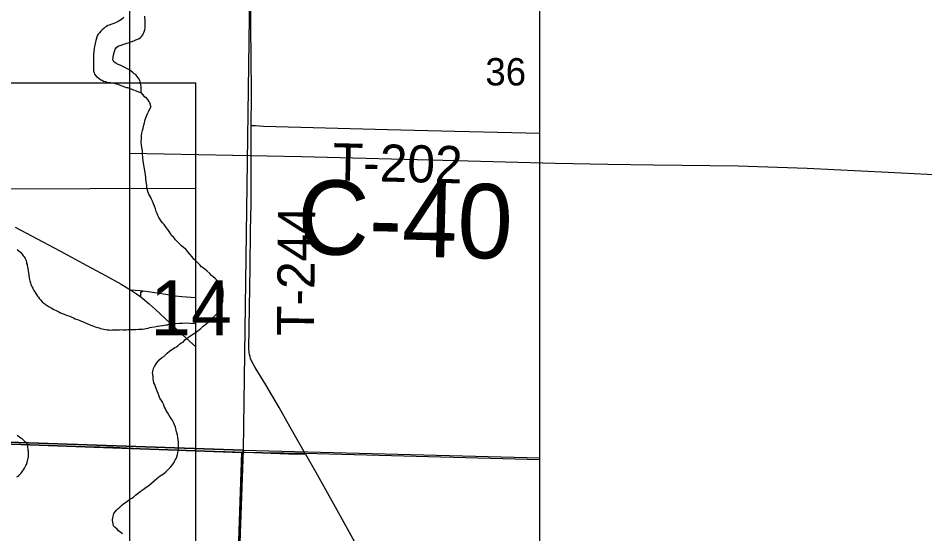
# Model space of a CAD drawing. Extents: x 0 to 68, y 0 to 52.9.
# Drawn here: x 49.292 to 51.122, y 37.625 to 38.666 of the extents above; entities that cross this region are included whole.
import ezdxf

# ---------------------------------------------------------------- set-up
doc = ezdxf.new("R2010")
doc.units = 0
for name, color, linetype in [('Default', 7, 'Continuous'), ('GM_X_County_Road', 7, 'Continuous'), ('GM_X_County_Road_Text', 7, 'Continuous'), ('GM_X_Minor_River', 7, 'Continuous'), ('GM_X_State_Route', 7, 'Continuous'), ('GM_X_Township', 7, 'Continuous'), ('GM_X_Township_Road', 7, 'Continuous'), ('GM_X_Township_Road_Text', 7, 'Continuous')]:
    doc.layers.add(name, color=color, linetype=linetype)

msp = doc.modelspace()

# ---------------------------------------------------------------- linework, layer by layer
at = {"layer": 'Default'}
for p, q in [((49.5172, 34.4614), (49.5172, 52.9414)), ((50.3451, 32.7683), (50.3451, 42.0083)), ((42.2581, 38.5351), (49.6501, 38.5351)), ((49.6501, 31.1431), (49.6501, 38.5351))]:
    msp.add_line(p, q, dxfattribs=at)
for points in [[(49.764, 39.105), (49.7457, 37.7942), (48.4264, 37.8391), (48.4576, 39.1473)], [(48.4264, 37.8391), (49.7457, 37.7942), (49.6996, 36.5084), (48.3843, 36.5523)]]:
    msp.add_lwpolyline(points, close=True, dxfattribs=at)
for points in [[(49.5047, 38.6669), (49.5001, 38.6634), (49.4935, 38.659), (49.488, 38.6565), (49.4753, 38.6517), (49.4723, 38.6507), (49.4697, 38.6492), (49.4672, 38.6473), (49.4642, 38.6448), (49.4611, 38.6423), (49.4585, 38.6393), (49.4555, 38.6364), (49.4529, 38.6334), (49.4514, 38.6299), (49.4498, 38.6254), (49.4482, 38.6204), (49.4472, 38.6144), (49.4456, 38.6089), (49.445, 38.6044), (49.4444, 38.5983), (49.4438, 38.5923), (49.4438, 38.5868), (49.4437, 38.5803), (49.4436, 38.5753), (49.4436, 38.5707), (49.4435, 38.5657), (49.4439, 38.5597), (49.4449, 38.5556), (49.4459, 38.5531), (49.4498, 38.548), (49.4543, 38.5445), (49.4588, 38.5414), (49.4613, 38.5404), (49.4638, 38.5388), (49.4678, 38.5378), (49.4708, 38.5367), (49.4739, 38.5362), (49.4779, 38.5361), (49.4809, 38.5356), (49.4839, 38.535), (49.4869, 38.534), (49.4904, 38.5334), (49.493, 38.5329), (49.4975, 38.5308), (49.501, 38.5293), (49.5035, 38.5283), (49.506, 38.5272), (49.5095, 38.5262), (49.512, 38.5256), (49.5396, 38.5152)], [(49.5162, 38.617), (49.5187, 38.618), (49.5217, 38.6189), (49.5263, 38.6209), (49.5293, 38.6218), (49.5334, 38.6233), (49.5359, 38.6248), (49.5385, 38.6267), (49.541, 38.6292), (49.5431, 38.6322), (49.5446, 38.6352), (49.5462, 38.6382), (49.5472, 38.6422), (49.5478, 38.6462), (49.5478, 38.6502), (49.5479, 38.6542), (49.5479, 38.6578), (49.548, 38.6623), (49.5475, 38.6658), (49.5471, 38.6698)], [(49.5396, 38.5152), (49.5401, 38.5212), (49.5397, 38.5283), (49.5393, 38.5313), (49.5388, 38.5348), (49.5369, 38.5399), (49.5344, 38.5449), (49.5314, 38.5485), (49.529, 38.552), (49.526, 38.5536), (49.5235, 38.5556), (49.52, 38.5587), (49.5175, 38.5602), (49.515, 38.5623), (49.5115, 38.5638), (49.507, 38.5659), (49.504, 38.5679), (49.5005, 38.5695), (49.4975, 38.571), (49.4935, 38.5726), (49.489, 38.5747), (49.4855, 38.5772), (49.483, 38.5818), (49.4836, 38.5873), (49.4841, 38.5918), (49.4873, 38.6033), (49.4904, 38.6068), (49.4939, 38.6102), (49.4975, 38.6107), (49.5015, 38.6122), (49.5045, 38.6131), (49.5076, 38.6141), (49.5106, 38.615), (49.5136, 38.616), (49.5162, 38.617)], [(49.6501, 38.3219), (49.2232, 38.3205), (49.2258, 38.5351)], [(49.5396, 38.5152), (49.5455, 38.5086), (49.5485, 38.5066), (49.553, 38.5015), (49.555, 38.4984), (49.5564, 38.4959), (49.5574, 38.4934), (49.5584, 38.4904), (49.5594, 38.4873), (49.5533, 38.4746)], [(49.5449, 38.447), (49.5454, 38.4496), (49.5459, 38.4521), (49.5469, 38.4551), (49.5474, 38.4581), (49.5479, 38.4611), (49.5494, 38.4646), (49.5533, 38.4746)], [(49.6015, 37.9969), (49.6051, 37.9994), (49.6081, 38.0014), (49.6111, 38.0029), (49.6136, 38.0044), (49.6176, 38.0079), (49.6206, 38.0104), (49.6247, 38.0123), (49.6282, 38.0169), (49.6352, 38.0218), (49.6423, 38.0268), (49.6488, 38.0308), (49.6548, 38.0358), (49.6604, 38.0398), (49.6654, 38.0443), (49.6704, 38.0483), (49.6754, 38.0523), (49.68, 38.0558), (49.683, 38.0588), (49.686, 38.0623), (49.69, 38.0663), (49.693, 38.0693), (49.6961, 38.0728), (49.6976, 38.0753), (49.6996, 38.0788), (49.7011, 38.0813), (49.7026, 38.0843), (49.7036, 38.0888), (49.7046, 38.0939), (49.7051, 38.0994), (49.7052, 38.1069), (49.7052, 38.1134), (49.7047, 38.1194), (49.7032, 38.124), (49.7012, 38.1285), (49.6987, 38.1315), (49.6892, 38.1406), (49.6852, 38.1436), (49.6817, 38.1466), (49.6782, 38.1506), (49.6727, 38.1557), (49.6692, 38.1587), (49.6657, 38.1612), (49.6616, 38.1642), (49.6581, 38.1683), (49.6541, 38.1723), (49.6501, 38.1763), (49.6461, 38.1798), (49.6426, 38.1844), (49.6381, 38.1899), (49.6341, 38.1944), (49.6301, 38.1994), (49.6251, 38.203), (49.6216, 38.2065), (49.6171, 38.2105), (49.6131, 38.2146), (49.6091, 38.2186), (49.6056, 38.2231), (49.6021, 38.2266), (49.5991, 38.2312), (49.5961, 38.2352), (49.5936, 38.2392), (49.5901, 38.2437), (49.5861, 38.2493), (49.5831, 38.2528), (49.5806, 38.2563), (49.5781, 38.2593), (49.5756, 38.2633), (49.5736, 38.2674), (49.5721, 38.2719), (49.5701, 38.2759), (49.5686, 38.2809), (49.5666, 38.2864), (49.5646, 38.291), (49.5631, 38.2965), (49.5606, 38.3005), (49.5591, 38.304), (49.5571, 38.3075), (49.5551, 38.3106), (49.5541, 38.3141), (49.5526, 38.3186), (49.5516, 38.3231), (49.5511, 38.3291), (49.5501, 38.3357), (49.5492, 38.3427), (49.5487, 38.3502), (49.5442, 38.3773), (49.5432, 38.3843), (49.5428, 38.3914), (49.5423, 38.3984), (49.5413, 38.4049), (49.5408, 38.4099), (49.5398, 38.414), (49.5398, 38.4175), (49.5403, 38.421), (49.5403, 38.4255), (49.5408, 38.429), (49.5413, 38.434), (49.5424, 38.439), (49.5439, 38.4435), (49.5449, 38.447)], [(49.5023, 37.625), (49.4998, 37.627), (49.4968, 37.629), (49.4943, 37.6315), (49.4913, 37.6345), (49.4873, 37.6381), (49.4843, 37.6411), (49.4833, 37.6456), (49.4828, 37.6491), (49.4823, 37.6521), (49.4823, 37.6546), (49.4828, 37.6571), (49.4834, 37.6607), (49.4849, 37.6662), (49.4874, 37.6697), (49.4904, 37.6727), (49.4934, 37.6762), (49.4969, 37.6792), (49.5005, 37.6822), (49.505, 37.6862), (49.5105, 37.6897), (49.5166, 37.6942), (49.5211, 37.6971), (49.5251, 37.7001), (49.5286, 37.7031), (49.5341, 37.7071), (49.5382, 37.7106), (49.5437, 37.7146), (49.5497, 37.7191), (49.5553, 37.7231), (49.5713, 37.7371), (49.5784, 37.7421), (49.5849, 37.7466), (49.5899, 37.7506), (49.594, 37.7546), (49.5975, 37.7581), (49.6, 37.7606), (49.6015, 37.7631), (49.6035, 37.7656), (49.6065, 37.7691), (49.6081, 37.7731), (49.6096, 37.7756), (49.6116, 37.7806), (49.6131, 37.7856), (49.6141, 37.7891), (49.6146, 37.7922), (49.6151, 37.7957), (49.6151, 37.8002), (49.6152, 37.8052), (49.6152, 37.8102), (49.6147, 37.8147), (49.6142, 37.8197), (49.6132, 37.8253), (49.6112, 37.8313), (49.6092, 37.8408), (49.6057, 37.8484), (49.6022, 37.8554), (49.5987, 37.8609), (49.5957, 37.8655), (49.5932, 37.87), (49.5907, 37.874), (49.5882, 37.8785), (49.5862, 37.882), (49.5847, 37.8866), (49.5827, 37.8906), (49.5807, 37.8941), (49.5777, 37.8991), (49.5762, 37.9031), (49.5742, 37.9082), (49.5723, 37.9132), (49.5703, 37.9182), (49.5688, 37.9217), (49.5673, 37.9263), (49.5658, 37.9298), (49.5648, 37.9338), (49.5643, 37.9383), (49.5638, 37.9428), (49.5628, 37.9503), (49.5633, 37.9529), (49.5638, 37.9559), (49.5648, 37.9589), (49.5668, 37.9629), (49.5699, 37.9684), (49.5754, 37.9754), (49.5809, 37.9804), (49.5855, 37.9829), (49.588, 37.9854), (49.5925, 37.9899), (49.597, 37.9939), (49.6015, 37.9969)], [(49.2887, 37.7403), (49.2928, 37.7422), (49.2948, 37.745), (49.2969, 37.747), (49.2989, 37.7494), (49.3006, 37.7518), (49.3026, 37.7546), (49.3043, 37.7578), (49.3059, 37.7606), (49.3071, 37.7629), (49.3084, 37.7653), (49.3096, 37.7689), (49.3113, 37.7754), (49.3118, 37.7778), (49.3122, 37.7802), (49.3122, 37.7834), (49.3123, 37.7866), (49.3123, 37.7894), (49.3123, 37.7918), (49.312, 37.7938), (49.312, 37.7958), (49.3112, 37.7999), (49.3109, 37.8019), (49.3101, 37.8043), (49.3097, 37.8063), (49.3081, 37.8087), (49.3061, 37.8104), (49.3038, 37.8132), (49.3018, 37.8149), (49.2994, 37.8169), (49.297, 37.8185), (49.2946, 37.8202), (49.2922, 37.8218), (49.2894, 37.8235)], [(50.3451, 36.4776), (49.6996, 36.5084), (49.7457, 37.7942), (50.3451, 37.7786)]]:
    msp.add_lwpolyline(points, dxfattribs=at)
at = {"layer": 'GM_X_County_Road'}
for points in [[(49.5172, 38.3936), (49.8634, 38.3865), (50.175, 38.3783), (50.3759, 38.3731), (50.4819, 38.3714)], [(50.4819, 38.3714), (50.5742, 38.3699), (50.7454, 38.3675), (50.8848, 38.363), (51.0482, 38.3553), (51.1794, 38.3484), (51.7594, 38.3186), (52.1274, 38.2999), (52.1467, 38.299)], [(49.5186, 38.1175), (49.5277, 38.1169), (49.5381, 38.1163), (49.5431, 38.1157)], [(49.5389, 38.1032), (49.539, 38.1082), (49.5392, 38.1104), (49.5395, 38.1114), (49.5404, 38.1134), (49.5431, 38.1157)], [(49.5431, 38.1157), (49.5538, 38.1145), (49.5894, 38.1086), (49.6089, 38.1055), (49.6219, 38.104), (49.6501, 38.1023)]]:
    msp.add_lwpolyline(points, dxfattribs=at)
at = {"layer": 'GM_X_Minor_River'}
for points in [[(49.2897, 38.1991), (49.2929, 38.1963), (49.2961, 38.1938), (49.2992, 38.1902), (49.302, 38.1861), (49.304, 38.1841), (49.3056, 38.1808), (49.3072, 38.178), (49.3075, 38.176), (49.3083, 38.1732), (49.3087, 38.1708), (49.3095, 38.1687), (49.3098, 38.1667), (49.3102, 38.1643), (49.311, 38.1607), (49.3128, 38.1474), (49.3139, 38.1414), (49.3151, 38.1357), (49.3162, 38.1317), (49.3174, 38.1289), (49.3186, 38.1256), (49.3198, 38.1232), (49.3209, 38.1208), (49.3217, 38.1188), (49.3233, 38.1163), (49.3249, 38.1139), (49.3272, 38.1102), (49.3284, 38.1082), (49.3308, 38.1046), (49.3324, 38.1025), (49.3344, 38.0997), (49.3364, 38.0977), (49.3403, 38.0932), (49.3431, 38.0907), (49.3451, 38.0891), (49.3475, 38.0875), (49.3499, 38.0858), (49.3519, 38.0846), (49.3543, 38.0834), (49.3571, 38.0817), (49.3595, 38.0805), (49.3623, 38.0788), (49.3651, 38.0772), (49.3683, 38.076), (49.3707, 38.0743), (49.3739, 38.0731), (49.3771, 38.0714), (49.3811, 38.0698), (49.3859, 38.0681), (49.3911, 38.066), (49.3956, 38.0643), (49.4, 38.0623), (49.4036, 38.061), (49.4068, 38.0594), (49.4112, 38.0577), (49.4144, 38.0565), (49.4176, 38.0548), (49.4212, 38.0536), (49.424, 38.0523), (49.4272, 38.0511), (49.4304, 38.0494), (49.4416, 38.0449)], [(49.4416, 38.0449), (49.4444, 38.044), (49.4472, 38.0428), (49.4517, 38.0415), (49.4549, 38.0407), (49.4581, 38.0398), (49.4609, 38.039), (49.4645, 38.0381), (49.4677, 38.0373), (49.4713, 38.0372), (49.475, 38.0368), (49.4786, 38.0363), (49.4814, 38.0367), (49.4842, 38.0367), (49.4887, 38.0366), (49.4923, 38.037), (49.4959, 38.0369), (49.4995, 38.0373), (49.5032, 38.0372), (49.5068, 38.0372), (49.5104, 38.0371), (49.5137, 38.0375), (49.5177, 38.0374), (49.5217, 38.0374), (49.5253, 38.0377), (49.529, 38.0377), (49.5342, 38.038), (49.5382, 38.038), (49.5423, 38.0383), (49.5467, 38.0387), (49.5503, 38.0394), (49.554, 38.0402), (49.5576, 38.0413), (49.5616, 38.0421), (49.5669, 38.0432), (49.573, 38.0443), (49.5778, 38.0451), (49.5834, 38.0458), (49.5871, 38.0466), (49.5903, 38.0469), (49.5931, 38.0473), (49.596, 38.0481), (49.6, 38.0484), (49.6048, 38.0491), (49.6089, 38.0495), (49.6165, 38.0502), (49.6198, 38.0506), (49.6234, 38.0505), (49.629, 38.0508), (49.6501, 38.0498)]]:
    msp.add_lwpolyline(points, dxfattribs=at)
at = {"layer": 'GM_X_State_Route'}
msp.add_lwpolyline([(49.2858, 38.2442), (49.3755, 38.1963), (49.4305, 38.1669), (49.4681, 38.1467), (49.4996, 38.129), (49.5186, 38.1175), (49.5302, 38.1097), (49.5389, 38.1032), (49.5434, 38.0999), (49.5561, 38.0895), (49.5685, 38.0787), (49.5877, 38.0607), (49.6232, 38.0266), (49.6501, 38.0023)], dxfattribs=at)
at = {"layer": 'GM_X_Township'}
for points in [[(50.3451, 37.7743), (49.87, 37.7873), (49.7424, 37.7891), (49.0919, 37.8129), (48.4292, 37.8378), (47.9758, 37.8521), (47.0934, 37.8749), (46.4354, 37.887), (45.7815, 37.9075), (45.7636, 37.9078), (44.7776, 37.9316), (44.1214, 37.9431), (43.3203, 37.9479), (43.3145, 37.9477), (43.1323, 37.9511), (43.1372, 38.1253), (43.1394, 38.1865), (43.1395, 38.194), (43.1504, 38.6162), (43.1581, 38.8961)], [(44.7776, 37.9316), (45.7636, 37.9078), (45.7815, 37.9075), (46.4354, 37.887), (47.0934, 37.8749), (47.9758, 37.8521), (48.4292, 37.8378), (49.0919, 37.8129), (49.7424, 37.7891), (49.7157, 36.9972), (49.7077, 36.748), (49.6951, 36.1805), (49.6872, 35.8521), (49.6545, 34.5254), (49.6326, 33.8658), (49.6189, 33.2067), (49.6098, 32.7683)]]:
    msp.add_lwpolyline(points, dxfattribs=at)
at = {"layer": 'GM_X_Township_Road'}
for points in [[(49.7623, 38.4494), (49.7624, 38.5084), (49.7617, 38.5946), (49.7613, 38.6397), (49.7616, 38.6931), (49.7624, 38.7464), (49.7623, 38.7996), (49.7632, 38.902), (49.7643, 39.0211), (49.7647, 39.0744), (49.7653, 39.1063)], [(49.8719, 37.7861), (49.841, 37.8408), (49.8186, 37.88), (49.7914, 37.9259), (49.7698, 37.9609), (49.7641, 37.9718), (49.7609, 37.9793), (49.7597, 37.9832), (49.7587, 37.9872), (49.758, 37.9912), (49.7575, 37.9994), (49.7602, 38.1636), (49.7606, 38.2375), (49.7617, 38.2908), (49.7622, 38.3852), (49.7623, 38.4494)], [(49.7623, 38.4494), (49.7706, 38.4489), (49.787, 38.4481), (50.0375, 38.4413), (50.173, 38.4376), (50.288, 38.435), (50.3451, 38.4339)], [(49.0928, 37.812), (49.1299, 37.8106), (49.2254, 37.808), (49.3111, 37.8053), (49.4277, 37.8015), (49.4838, 37.7998), (49.5639, 37.7964), (49.7497, 37.7898)], [(49.7497, 37.7898), (49.8374, 37.7867), (49.8719, 37.7861)], [(49.8719, 37.7861), (49.8924, 37.7499), (49.9385, 37.6675), (49.984, 37.5848)]]:
    msp.add_lwpolyline(points, dxfattribs=at)

# ---------------------------------------------------------------- texts
at = {"layer": 'Default'}
for s, height, p in [('36', 0.05525, (50.2348, 38.53)), ('14', 0.1105, (49.5584, 38.0261))]:
    msp.add_text(s, height=height, rotation=0, dxfattribs=at).set_placement(p)
at = {"layer": 'GM_X_County_Road_Text'}
msp.add_text('C-40', height=0.15, rotation=358.6287, dxfattribs=at).set_placement((49.8537, 38.1903))
at = {"layer": 'GM_X_Township_Road_Text'}
for s, rotation, p in [('T-202', 358.5957, (49.9261, 38.3387)), ('T-244', 89.4376, (49.8888, 38.0242))]:
    msp.add_text(s, height=0.075, rotation=rotation, dxfattribs=at).set_placement(p)

doc.saveas('drawing.dxf')
